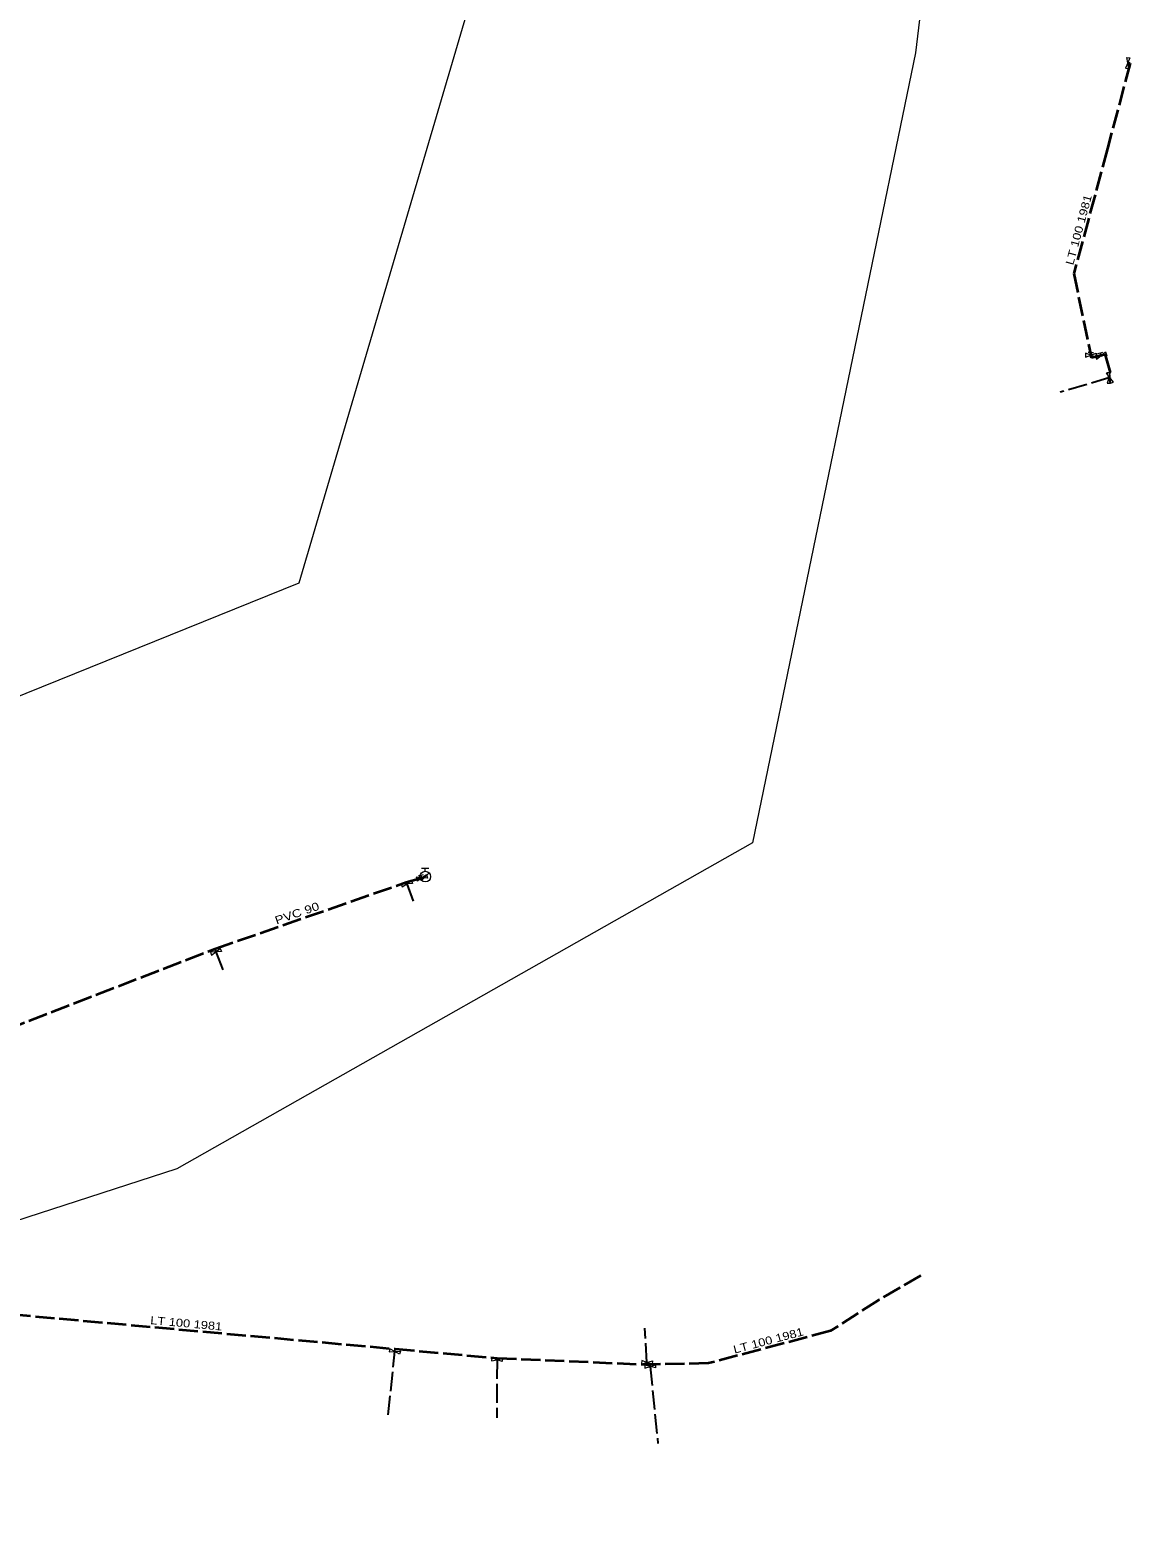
# Model space of a CAD drawing. Extents: x -616592 to -615844, y -1088988 to -1088174.
# Drawn here: x -615946.8 to -615843.6, y -1088431.2 to -1088291 of the extents above; entities that cross this region are included whole.
import ezdxf
from ezdxf.enums import TextEntityAlignment as Align

# ---------------------------------------------------------------- set-up
doc = ezdxf.new("R2010")
doc.units = 0
doc.header["$LTSCALE"] = 0.3
doc.linetypes.add('LONG_DASHED', pattern=[7.5, 6, -1.5])
for name, color, linetype, lineweight in [('1', 7, 'Continuous', 13), ('10', 7, 'Continuous', 13), ('35', 7, 'LONG_DASHED', 35), ('50', 7, 'LONG_DASHED', 25)]:
    doc.layers.add(name, color=color, linetype=linetype, lineweight=lineweight)
doc.layers.add('16', color=7, linetype='Continuous')

msp = doc.modelspace()

# ---------------------------------------------------------------- linework, layer by layer
at = {"layer": '1'}
msp.add_lwpolyline([(-616317.402, -1088743.479), (-616316.925, -1088623.142), (-616336.026, -1088584.94), (-616318.357, -1088562.497), (-616286.363, -1088552.469), (-616214.734, -1088468.424), (-616144.06, -1088425.447), (-616043.302, -1088392.02), (-615921.533, -1088342.835), (-615901, -1088273.116), (-615900.045, -1088185.251), (-615900.045, -1088185.251), (-615851.337, -1088190.027), (-615863.753, -1088293.172), (-615879.033, -1088367.189), (-615932.994, -1088397.75), (-616036.139, -1088431.177), (-616143.105, -1088462.216), (-616202.318, -1088518.087), (-616257.711, -1088587.328), (-616274.902, -1088683.788)], dxfattribs=at)
at = {"layer": '10'}
for p, q in [((-615847.332, -1088321.252), (-615847.582, -1088321.252)), ((-615846.446, -1088321.311), (-615846.682, -1088321.394)), ((-615910.054, -1088370.714), (-615909.347, -1088370.007)), ((-615910.05, -1088369.56), (-615909.35, -1088369.56)), ((-615909.7, -1088369.86), (-615909.7, -1088369.56)), ((-615910.094, -1088370.218), (-615910.336, -1088370.282))]:
    msp.add_line(p, q, dxfattribs=at)
for points in [[(-615843.86, -1088294.12), (-615843.95, -1088293.606), (-615843.652, -1088293.641), (-615843.86, -1088294.12), (-615844.068, -1088294.599), (-615843.77, -1088294.634)], [(-615845.53, -1088323.61), (-615845.85, -1088323.198), (-615845.57, -1088323.09), (-615845.53, -1088323.61), (-615845.49, -1088324.13), (-615845.21, -1088324.022)], [(-615845.644, -1088323.612), (-615845.794, -1088323.112), (-615845.494, -1088323.112), (-615845.644, -1088323.612), (-615845.794, -1088324.112), (-615845.494, -1088324.112)], [(-615911.43, -1088371.02), (-615910.997, -1088370.729), (-615910.908, -1088371.015), (-615911.43, -1088371.02), (-615911.952, -1088371.025), (-615911.863, -1088371.311)], [(-615929.32, -1088377.4), (-615928.907, -1088377.081), (-615928.799, -1088377.361), (-615929.32, -1088377.4), (-615929.841, -1088377.439), (-615929.733, -1088377.719)], [(-615912.556, -1088414.858), (-615912.036, -1088414.817), (-615912.099, -1088415.11), (-615912.556, -1088414.858), (-615913.013, -1088414.606), (-615913.076, -1088414.899)], [(-615902.97, -1088415.62), (-615902.461, -1088415.505), (-615902.482, -1088415.804), (-615902.97, -1088415.62), (-615903.458, -1088415.436), (-615903.479, -1088415.735)], [(-615888.92, -1088415.87), (-615888.416, -1088415.734), (-615888.424, -1088416.034), (-615888.92, -1088415.87), (-615889.416, -1088415.706), (-615889.424, -1088416.006)], [(-615888.61, -1088416.26), (-615888.114, -1088416.098), (-615888.107, -1088416.398), (-615888.61, -1088416.26), (-615889.113, -1088416.122), (-615889.106, -1088416.422)]]:
    msp.add_lwpolyline(points, close=True, dxfattribs=at)
for points in [[(-615847.332, -1088321.502), (-615846.832, -1088321.315), (-615846.832, -1088321.689), (-615847.332, -1088321.502), (-615847.832, -1088321.315), (-615847.832, -1088321.689), (-615847.332, -1088321.502), (-615847.332, -1088321.252), (-615847.082, -1088321.252)], [(-615846.363, -1088321.547), (-615845.953, -1088321.205), (-615845.829, -1088321.558), (-615846.363, -1088321.547), (-615846.897, -1088321.536), (-615846.773, -1088321.889), (-615846.363, -1088321.547), (-615846.446, -1088321.311), (-615846.21, -1088321.228)], [(-615910.03, -1088370.46), (-615909.594, -1088370.152), (-615909.499, -1088370.513), (-615910.03, -1088370.46), (-615910.561, -1088370.407), (-615910.466, -1088370.768), (-615910.03, -1088370.46), (-615910.094, -1088370.218), (-615909.852, -1088370.154)]]:
    msp.add_lwpolyline(points, dxfattribs=at)
msp.add_circle((-615909.6998, -1088370.3597), 0.5, dxfattribs=at)
at = {"layer": '35'}
for p, q in [((-615846.363, -1088321.547), (-615846.011, -1088321.391)), ((-615846.011, -1088321.391), (-615845.37, -1088323.57)), ((-615929.43, -1088377.13), (-615911.49, -1088370.89)), ((-615911.49, -1088370.89), (-615910.03, -1088370.46)), ((-615910.03, -1088370.46), (-615909.7, -1088370.36)), ((-615999.31, -1088404.19), (-615929.43, -1088377.13)), ((-615902.96, -1088415.47), (-615888.91, -1088416.07)), ((-615888.91, -1088416.07), (-615888.65, -1088416.07))]:
    msp.add_line(p, q, dxfattribs=at)
for points in [[(-615843.64, -1088294.16), (-615845.755, -1088302.152), (-615848.917, -1088313.858), (-615847.332, -1088321.502)], [(-615846.363, -1088321.547), (-615847.26, -1088321.766), (-615847.332, -1088321.502)], [(-615863.26, -1088407.72), (-615867.225, -1088410.048), (-615871.72, -1088412.93), (-615883.16, -1088415.96), (-615888.65, -1088416.07)], [(-615950.72, -1088411.16), (-615912.516, -1088414.608), (-615902.96, -1088415.47)]]:
    msp.add_lwpolyline(points, dxfattribs=at)
at = {"layer": '50'}
for p, q in [((-615843.64, -1088294.16), (-615843.86, -1088294.12)), ((-615845.53, -1088323.61), (-615850.196, -1088324.973)), ((-615911.49, -1088370.89), (-615911.43, -1088371.02)), ((-615911.43, -1088371.02), (-615910.823, -1088372.647)), ((-615929.43, -1088377.13), (-615929.32, -1088377.4)), ((-615929.32, -1088377.4), (-615928.6, -1088379.31)), ((-615888.92, -1088415.87), (-615889.122, -1088412.666)), ((-615913.169, -1088420.798), (-615912.556, -1088414.858)), ((-615912.556, -1088414.858), (-615912.516, -1088414.608)), ((-615902.97, -1088415.62), (-615902.998, -1088421.063)), ((-615902.96, -1088415.47), (-615902.97, -1088415.62)), ((-615888.91, -1088416.07), (-615888.92, -1088415.87)), ((-615888.65, -1088416.07), (-615888.61, -1088416.26)), ((-615888.61, -1088416.26), (-615887.9, -1088423.457))]:
    msp.add_line(p, q, dxfattribs=at)

# ---------------------------------------------------------------- texts
at = {"layer": '16'}
for s, rotation, width, p in [('LT 100 1981', 74.884, 1.2, (-615848.0949, -1088309.8558)), ('PVC 90', 19.179, 1.25, (-615921.5952, -1088374.1409)), ('LT 100 1981', 354.843, 1.2, (-615932.1322, -1088412.5862)), ('LT 100 1981', 14.835, 1.2, (-615877.445, -1088414.1884))]:
    msp.add_text(s, height=0.75, rotation=rotation, dxfattribs=dict(at, width=width)).set_placement(p, align=Align.CENTER)

doc.saveas('drawing.dxf')
